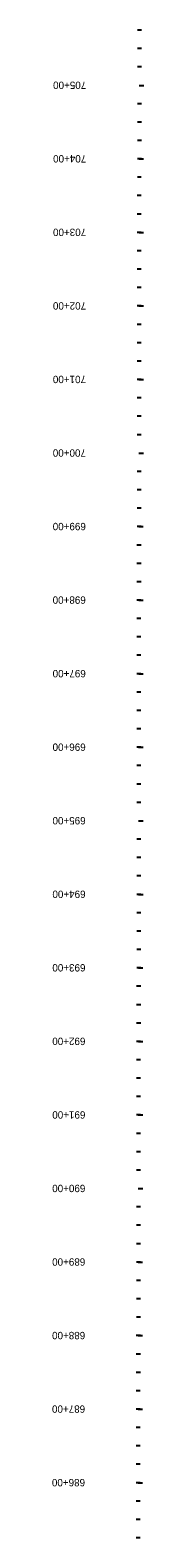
# Model space of a CAD drawing. Extents: x 16453950 to 16454580, y 7022804 to 7039381.
# Drawn here: x 16454325 to 16454449, y 7035265 to 7037315 of the extents above; entities that cross this region are included whole.
import ezdxf

# ---------------------------------------------------------------- set-up
doc = ezdxf.new("R2010")
doc.units = 0
doc.layers.add('TextAlignmentLrg', color=7, linetype='Continuous')
doc.layers.add('TextAlignmentSml', color=7, linetype='Continuous')

msp = doc.modelspace()

# ---------------------------------------------------------------- linework, layer by layer
at = {"layer": 'TextAlignmentLrg'}
for p, q in [((16454443.2, 7037239.6), (16454449.3, 7037239.6)), ((16454446.2, 7037139.6), (16454440.7, 7037139.6)), ((16454446.1, 7037039.6), (16454440.6, 7037039.6)), ((16454446, 7036939.6), (16454440.5, 7036939.6)), ((16454445.9, 7036839.6), (16454440.4, 7036839.6)), ((16454442.8, 7036739.6), (16454448.9, 7036739.6)), ((16454445.7, 7036639.6), (16454440.3, 7036639.6)), ((16454445.6, 7036539.6), (16454440.2, 7036539.6)), ((16454445.6, 7036439.6), (16454440.1, 7036439.6)), ((16454445.5, 7036339.6), (16454440, 7036339.6)), ((16454442.3, 7036239.6), (16454448.5, 7036239.6)), ((16454445.3, 7036139.6), (16454439.8, 7036139.6)), ((16454445.2, 7036039.6), (16454439.8, 7036039.6)), ((16454445.1, 7035939.6), (16454439.7, 7035939.6)), ((16454445.1, 7035839.6), (16454439.6, 7035839.6)), ((16454441.9, 7035739.6), (16454448, 7035739.6)), ((16454444.9, 7035639.6), (16454439.4, 7035639.6)), ((16454444.8, 7035539.6), (16454439.3, 7035539.6)), ((16454444.7, 7035439.6), (16454439.3, 7035439.6)), ((16454444.6, 7035339.6), (16454439.2, 7035339.6))]:
    msp.add_line(p, q, dxfattribs=at)
at = {"layer": 'TextAlignmentSml'}
for p, q in [((16454446.3, 7037314.6), (16454440.8, 7037314.6)), ((16454446.3, 7037289.6), (16454440.8, 7037289.6)), ((16454446.3, 7037264.6), (16454440.8, 7037264.6)), ((16454443.2, 7037239.6), (16454449.3, 7037239.6)), ((16454446.2, 7037214.6), (16454440.8, 7037214.6)), ((16454446.2, 7037189.6), (16454440.7, 7037189.6)), ((16454446.2, 7037164.6), (16454440.7, 7037164.6)), ((16454443.1, 7037139.6), (16454449.2, 7037139.6)), ((16454446.1, 7037114.6), (16454440.7, 7037114.6)), ((16454446.1, 7037089.6), (16454440.6, 7037089.6)), ((16454446.1, 7037064.6), (16454440.6, 7037064.6)), ((16454443, 7037039.6), (16454449.1, 7037039.6)), ((16454446, 7037014.6), (16454440.6, 7037014.6)), ((16454446, 7036989.6), (16454440.6, 7036989.6)), ((16454446, 7036964.6), (16454440.5, 7036964.6)), ((16454442.9, 7036939.6), (16454449, 7036939.6)), ((16454446, 7036914.6), (16454440.5, 7036914.6)), ((16454445.9, 7036889.6), (16454440.5, 7036889.6)), ((16454445.9, 7036864.6), (16454440.5, 7036864.6)), ((16454442.8, 7036839.6), (16454449, 7036839.6)), ((16454445.9, 7036814.6), (16454440.4, 7036814.6)), ((16454445.9, 7036789.6), (16454440.4, 7036789.6)), ((16454445.8, 7036764.6), (16454440.4, 7036764.6)), ((16454442.8, 7036739.6), (16454448.9, 7036739.6)), ((16454445.8, 7036714.6), (16454440.3, 7036714.6)), ((16454445.8, 7036689.6), (16454440.3, 7036689.6)), ((16454445.8, 7036664.6), (16454440.3, 7036664.6)), ((16454442.7, 7036639.6), (16454448.8, 7036639.6)), ((16454445.7, 7036614.6), (16454440.2, 7036614.6)), ((16454445.7, 7036589.6), (16454440.2, 7036589.6)), ((16454445.7, 7036564.6), (16454440.2, 7036564.6)), ((16454442.6, 7036539.6), (16454448.7, 7036539.6)), ((16454445.6, 7036514.6), (16454440.2, 7036514.6)), ((16454445.6, 7036489.6), (16454440.1, 7036489.6)), ((16454445.6, 7036464.6), (16454440.1, 7036464.6)), ((16454442.5, 7036439.6), (16454448.6, 7036439.6)), ((16454445.5, 7036414.6), (16454440.1, 7036414.6)), ((16454445.5, 7036389.6), (16454440.1, 7036389.6)), ((16454445.5, 7036364.6), (16454440, 7036364.6)), ((16454442.4, 7036339.6), (16454448.5, 7036339.6)), ((16454445.5, 7036314.6), (16454440, 7036314.6)), ((16454445.4, 7036289.6), (16454440, 7036289.6)), ((16454445.4, 7036264.6), (16454440, 7036264.6)), ((16454442.3, 7036239.6), (16454448.5, 7036239.6)), ((16454445.4, 7036214.6), (16454439.9, 7036214.6)), ((16454445.4, 7036189.6), (16454439.9, 7036189.6)), ((16454445.3, 7036164.6), (16454439.9, 7036164.6)), ((16454442.2, 7036139.6), (16454448.4, 7036139.6)), ((16454445.3, 7036114.6), (16454439.8, 7036114.6)), ((16454445.3, 7036089.6), (16454439.8, 7036089.6)), ((16454445.2, 7036064.6), (16454439.8, 7036064.6)), ((16454442.2, 7036039.6), (16454448.3, 7036039.6)), ((16454445.2, 7036014.6), (16454439.7, 7036014.6)), ((16454445.2, 7035989.6), (16454439.7, 7035989.6)), ((16454445.2, 7035964.6), (16454439.7, 7035964.6)), ((16454442.1, 7035939.6), (16454448.2, 7035939.6)), ((16454445.1, 7035914.6), (16454439.7, 7035914.6)), ((16454445.1, 7035889.6), (16454439.6, 7035889.6)), ((16454445.1, 7035864.6), (16454439.6, 7035864.6)), ((16454442, 7035839.6), (16454448.1, 7035839.6)), ((16454445, 7035814.6), (16454439.6, 7035814.6)), ((16454445, 7035789.6), (16454439.6, 7035789.6)), ((16454445, 7035764.6), (16454439.5, 7035764.6)), ((16454441.9, 7035739.6), (16454448, 7035739.6)), ((16454444.9, 7035714.6), (16454439.5, 7035714.6)), ((16454444.9, 7035689.6), (16454439.5, 7035689.6)), ((16454444.9, 7035664.6), (16454439.4, 7035664.6)), ((16454441.8, 7035639.6), (16454447.9, 7035639.6)), ((16454444.9, 7035614.6), (16454439.4, 7035614.6)), ((16454444.8, 7035589.6), (16454439.4, 7035589.6)), ((16454444.8, 7035564.6), (16454439.4, 7035564.6)), ((16454441.7, 7035539.6), (16454447.9, 7035539.6)), ((16454444.8, 7035514.6), (16454439.3, 7035514.6)), ((16454444.8, 7035489.6), (16454439.3, 7035489.6)), ((16454444.7, 7035464.6), (16454439.3, 7035464.6)), ((16454441.7, 7035439.6), (16454447.8, 7035439.6)), ((16454444.7, 7035414.6), (16454439.2, 7035414.6)), ((16454444.7, 7035389.6), (16454439.2, 7035389.6)), ((16454444.7, 7035364.6), (16454439.2, 7035364.6)), ((16454441.6, 7035339.6), (16454447.7, 7035339.6)), ((16454444.6, 7035314.6), (16454439.2, 7035314.6)), ((16454444.6, 7035289.6), (16454439.1, 7035289.6)), ((16454444.6, 7035264.6), (16454439.1, 7035264.6))]:
    msp.add_line(p, q, dxfattribs=at)

# ---------------------------------------------------------------- texts
at = {"layer": 'TextAlignmentLrg'}
for s, p in [('705+00', (16454371.2, 7037244.7)), ('700+00', (16454370.8, 7036744.7)), ('695+00', (16454370.4, 7036244.7)), ('690+00', (16454370, 7035744.7))]:
    msp.add_text(s, height=10.02, rotation=179.9517, dxfattribs=at).set_placement(p)
at = {"layer": 'TextAlignmentSml'}
for s, p in [('705+00', (16454371.2, 7037244.7)), ('704+00', (16454371.2, 7037144.7)), ('703+00', (16454371.1, 7037044.7)), ('702+00', (16454371, 7036944.7)), ('701+00', (16454370.9, 7036844.7)), ('700+00', (16454370.8, 7036744.7)), ('699+00', (16454370.7, 7036644.7)), ('698+00', (16454370.6, 7036544.7)), ('697+00', (16454370.6, 7036444.7)), ('696+00', (16454370.5, 7036344.7)), ('695+00', (16454370.4, 7036244.7)), ('694+00', (16454370.3, 7036144.7)), ('693+00', (16454370.2, 7036044.7)), ('692+00', (16454370.1, 7035944.7)), ('691+00', (16454370.1, 7035844.7)), ('690+00', (16454370, 7035744.7)), ('689+00', (16454369.9, 7035644.7)), ('688+00', (16454369.8, 7035544.7)), ('687+00', (16454369.7, 7035444.7)), ('686+00', (16454369.6, 7035344.7))]:
    msp.add_text(s, height=10.02, rotation=179.9517, dxfattribs=at).set_placement(p)

doc.saveas('drawing.dxf')
